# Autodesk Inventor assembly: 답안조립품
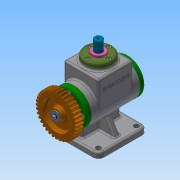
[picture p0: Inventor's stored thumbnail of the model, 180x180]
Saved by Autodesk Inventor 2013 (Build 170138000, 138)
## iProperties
Created: 2019-01
Part Number: 답안조립품
Document SubType Name: Assembly
Designer: Administrator
Mass: 1743.45 g
Surface Area: 1517.21 cm^2
Volume: 492.002 cm^3
Density: 3.54359 g/cm^3
Author: Administrator
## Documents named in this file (18)
- C:\Users\Administrator\Desktop\390107V1046\답안조립품.iam
- C:\Users\Administrator\Desktop\390107V1046\본체.ipt
- C:\Users\Administrator\Desktop\390107V1046\베어링 6203.ipt
- C:\Users\Administrator\Desktop\390107V1046\뒤커버.ipt
- C:\Users\Administrator\Desktop\390107V1046\볼트 M4.ipt
- C:\Users\Administrator\Desktop\390107V1046\편심축.ipt
- C:\Users\Administrator\Desktop\390107V1046\앞커버.ipt
- C:\Users\Administrator\Desktop\390107V1046\오일 실 17 30 5.ipt
- C:\Users\Administrator\Desktop\390107V1046\스퍼기어.ipt
- C:\Users\Administrator\Desktop\390107V1046\키 4x4x12.ipt
- C:\Users\Administrator\Desktop\390107V1046\평와셔.ipt
- C:\Users\Administrator\Desktop\390107V1046\스프링와셔.ipt
- C:\Users\Administrator\Desktop\390107V1046\슬라이더.ipt
- C:\Users\Administrator\Desktop\390107V1046\스프링조립용 와셔.ipt
- C:\Users\Administrator\Desktop\390107V1046\멈춤링.ipt
- C:\Users\Administrator\Desktop\390107V1046\부시.ipt
- C:\Users\Administrator\Desktop\390107V1046\상부커버.ipt
- C:\Users\Administrator\Desktop\390107V1046\가변스프링.ipt
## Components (1 placed, 1 different names)
1. 가변스프링:1
